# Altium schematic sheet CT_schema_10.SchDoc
size 274 x 160 mm
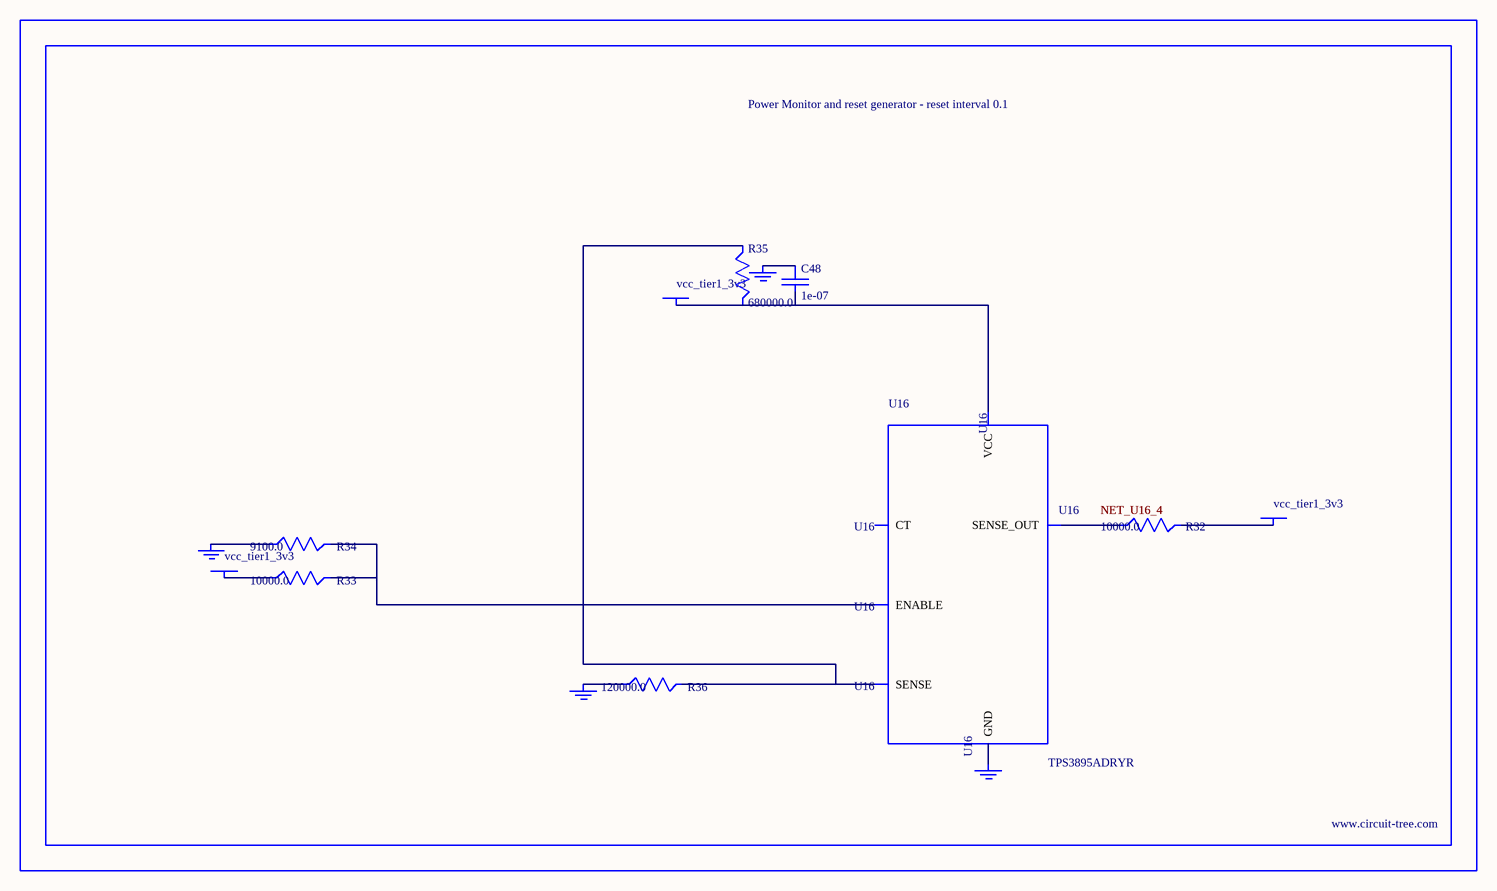
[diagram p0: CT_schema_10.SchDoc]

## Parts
BORDER9  (no value)
C48  1e-07  [C0402]
GND_INSTANCE_9_0  (no value)
GND_INSTANCE_9_1  (no value)
GND_INSTANCE_9_2  (no value)
GND_INSTANCE_9_3  (no value)
POWER_INSTANCE_9_0  vcc_tier1_3v3
POWER_INSTANCE_9_1  vcc_tier1_3v3
POWER_INSTANCE_9_2  vcc_tier1_3v3
R32  10000.0  [R0603]
R33  10000.0  [R0603]
R34  9100.0  [R0603]
R35  680000.0  [R0603]
R36  120000.0  [R0603]
U16  TPS3895ADRYR  [SON-6]

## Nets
NetC48_1: C48.1 GND_INSTANCE_9_2.0(GND)
NetC48_2: C48.2 POWER_INSTANCE_9_2.0(PWR) R35.2 U16.6(VCC)
NetGND_INSTANCE_9_0_0: GND_INSTANCE_9_0.0(GND) R34.1
NetGND_INSTANCE_9_1_0: GND_INSTANCE_9_1.0(GND) R36.1
NetGND_INSTANCE_9_3_0: GND_INSTANCE_9_3.0(GND) U16.2(GND)
NetPOWER_INSTANCE_9_0_0: POWER_INSTANCE_9_0.0(PWR) R33.1
NetPOWER_INSTANCE_9_1_0: POWER_INSTANCE_9_1.0(PWR) R32.2
NetR32_1: R32.1 U16.4(SENSE_OUT)
NetR33_2: R33.2 R34.2 U16.1(ENABLE)
NetR35_1: R35.1 R36.2 U16.3(SENSE)

Not connected (* = marked no-connect by the designer): U16 5(CT)

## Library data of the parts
BORDER9 = BORDER_PAGE9
C48 = C0402C104K3RACTU
GND_INSTANCE_9_0-GND_INSTANCE_9_3 = GND
POWER_INSTANCE_9_0-POWER_INSTANCE_9_2 = PWR
R32 R33 = RC0603JR-0710KL
R34 = RC0603JR-079K1L
R35 = RC0603JR-07680KL
R36 = RC0603JR-07120KL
